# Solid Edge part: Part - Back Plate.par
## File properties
Author: hhakima
Template: Normal.par
Last saved by: Houman
Revision: 22
Application: Solid Edge
Material: Aluminum, 6061-T6
Face Style: Aluminum
Fill Style: ANSI38(Aluminum)
Virtual Style: Polished aluminum
Coef. of Thermal Exp: 2.3e-05
Thermal Conductivity: 180.0
Specific Heat: 920.0
Modulus of Elasticity: 68947570000.0
Poission's Ratio: 0.33
Yield Stress: 275790280.0
Ultimate Stress: 310264065.0
Elongation: 0.0
Density: 2712.000 kg/m^3
Accuracy: 0.990
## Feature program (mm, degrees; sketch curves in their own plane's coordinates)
sketch for "unnamed Protrusion 1" plane through (0, 0, 0) normal (0, 0, 1) x-axis (1, 0, 0)
  line (-23.1805, 6.5797) -> (-23.1805, -13.4203)
  line (-23.1805, -13.4203) -> (-3.1805, -13.4203)
  line (-3.1805, -13.4203) -> (-3.1805, 6.5797)
  line (-3.1805, 6.5797) -> (-23.1805, 6.5797)
extrude "unnamed Protrusion 1" add finite 3 along +normal
sketch for "ExtrudedCutout_1" plane through (-10.6805, -0.9203, 3) normal (0, 0, 1) x-axis (1, 0, 0)
  circle centre (-2.5, -2.5) radius 7.25
  dimension (linear) = 2.5
extrude "ExtrudedCutout_1" cut finite 1 along -normal
sketch for "ExtrudedCutout_2" plane through (-10.6805, -0.9203, 2) normal (0, 0, 1) x-axis (1, 0, 0)
  circle centre (-2.5, -2.5) radius 3
extrude "ExtrudedCutout_2" cut finite 3 along -normal
sketch for "Hole_1" plane through (-10.6805, -0.9203, 3) normal (0, 0, 1) x-axis (1, 0, 0)
  hole centre (5.3, 5.3) bore radius 1.35
hole "Hole_1" diameter 2.7 finite
sketch for "unnamed Hole 1" plane through (-10.6805, -0.9203, 3) normal (0, 0, 1) x-axis (1, 0, 0)
  hole centre (5.3, -10.3) bore radius 1.35
hole "unnamed Hole 1" finite
sketch for "unnamed Hole 2" plane through (-10.6805, -0.9203, 3) normal (0, 0, 1) x-axis (1, 0, 0)
  hole centre (-10.3, -10.3) bore radius 1.35
hole "unnamed Hole 2" finite
sketch for "unnamed Hole 3" plane through (-10.6805, -0.9203, 3) normal (0, 0, 1) x-axis (1, 0, 0)
  hole centre (-10.3, 5.3) bore radius 1.35
  dimension (linear) = 10.3
  dimension (linear) = 5.3
  dimension (linear) = 5.3
hole "unnamed Hole 3" finite
pattern "unnamed Pattern 1" of "Hole_1", "unnamed Hole 1", "unnamed Hole 2", "unnamed Hole 3"
sketch for "ExtrudedCutout_3" #1 plane through (-10.6805, -0.9203, 0) normal (0, 0, -1) x-axis (-1, 0, 0)
  circle centre (10.3, 5.3) radius 4
sketch for "ExtrudedCutout_3" #2 plane through (-10.6805, -0.9203, 0) normal (0, 0, -1) x-axis (-1, 0, 0)
  circle centre (-5.3, 5.3) radius 4
sketch for "ExtrudedCutout_3" #3 plane through (-10.6805, -0.9203, 0) normal (0, 0, -1) x-axis (-1, 0, 0)
  circle centre (10.3, -10.3) radius 4
sketch for "ExtrudedCutout_3" #4 plane through (-10.6805, -0.9203, 0) normal (0, 0, -1) x-axis (-1, 0, 0)
  circle centre (-5.3, -10.3) radius 4
extrude "ExtrudedCutout_3" cut finite 1.5 along -normal
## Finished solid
Body 1: solid body, 21 faces, 48 edges, 24 vertices.
  Faces by surface: plane 11, cylinder 10
  Edges by curve: line 28, circle 20
Bounding box of the edges (mm): 20.000 x 20.000 x 3.000, from (-23.1805, -13.4203, 0) to (-3.1805, 6.5797, 3).
Cylindrical faces by radius (mm): R1.35 x4, R3 x1, R4 x4, R7.25 x1
Planar faces by outward normal: +x 1, +y 1, +z 2, -x 1, -y 1, -z 5
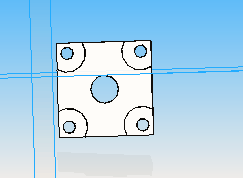
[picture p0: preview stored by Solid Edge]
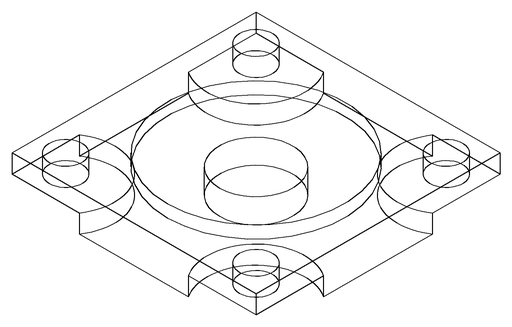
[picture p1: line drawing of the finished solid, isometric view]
